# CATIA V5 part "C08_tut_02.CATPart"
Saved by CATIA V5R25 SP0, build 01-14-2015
Part number: Part1
Bounding box of the stored display mesh (mm): x -50.5 to 35, y -44.806 to 44.806, z 0 to 30
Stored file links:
  E:\ashutosh\Academics\Catia\CATIA V5-6R2013_partfiles\Tutorials_ver_2\C08_tut_02.CATPart
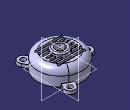
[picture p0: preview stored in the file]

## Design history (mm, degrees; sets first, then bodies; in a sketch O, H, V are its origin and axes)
Body1 (main body)
  Sketch1 on yz-plane, origin (0, 0, 0), H (0, 1, 0), V (0, 0, 1)
    line L1 (0, 0) -> (0, 25)
    line L2 (0, 25) -> (25, 25)
    point P2 (35, 25)
    line L3 (35, 15) -> (35, 0)
    point P3 (35, 0)
    line L4 (35, 0) -> (0, 0)
    reference intersected line E1 through (0, 0) direction (0, 1) from zx-plane
    axis line L5 (0, 41.2428) -> (0, -12.5007)
    point P4 (0, 41.2428)
    arc A1 centre (25, 15) radius 10 from (25, 25) to (35, 15) cw
    radius about axis P3 L5 = 35
    distance P2 P3 = 25
    radius A1 = 10
    horizontal: L2 H, L4 H
    coincidence: P3 H, L1 E1, P4 L1, L2 P2, L3 P2
    vertical: L3 V, L5 V
    tangency: A1 L2, A1 L3
  Shaft1: profile Sketch1, axis Sketch1.L5, angle 360
  Shell1: ExtOffset 0, Face face of Shaft1 from Sketch1.L4, IntOffset 3
  Sketch2 on face of Shaft1 from Sketch1.L4, origin (0, 0, 0), H (1, 0, 0), V (0, -1, 0)
    projected circle E1 centre (0, 0) radius 35 from edge [face of Shaft1 from Sketch1.L3 | face of Shaft1 from Sketch1.L4]
    projected arc E2 centre (0, 0) radius 35 from (-34.0735, 8) to (-34.0735, -8) ccw from edge [face of Shaft1 from Sketch1.L3 | face of Shaft1 from Sketch1.L4]
    point P1 (-34.0735, 8)
    line L1 (-34.0735, 8) -> (-42.5, 8)
    arc A1 centre (-42.5, 0) radius 8 from (-42.5, 8) to (-42.5, -8) ccw
    point P3 (-42.5, 0)
    line L2 (-42.5, -8) -> (-34.0735, -8)
    point P5 (-34.0735, -8)
    circle A2 centre (-42.5, 0) radius 4
    radius A1 = 8
    radius A2 = 4
    distance P3 V = 42.5
    coincidence: P1 E1, P3 H, P5 E1
    horizontal: L1 H, L2 H
    tangency: A1 L1, L2 A1
  Pad1: profile Sketch2, direction (0, 0, 1), length 5
  CircPattern1: of Pad1, instances 3, angular step 120 {= 360.0*1 deg/CircPattern1.AngularNumber}, axis from face of Shaft1 from Sketch1.L3
  Sketch3 on face of Shaft1 from Sketch1.L2, origin (0, 0, 25), H (1, 0, 0), V (0, 1, 0)
    point P1 (0, -18)
    line L1 (20, -19.75) -> (-20, -19.75)
    line L2 (-20, -16.25) -> (20, -16.25)
    point P5 (-20, -16.25)
    point P6 (20, -18)
    point P7 (-20, -18)
    arc A1 centre (20, -18) radius 1.75 from (20, -19.75) to (20, -16.25) ccw
    arc A2 centre (-20, -18) radius 1.75 from (-20, -16.25) to (-20, -19.75) ccw
    point P8 (-20, -16.25)
    axis line L3 (20, -18) -> (-20, -18)
    distance P7 P6 = 40
    distance H P6 = 18
    distance L2 L1 = 3.5
    coincidence: P1 V, A2 P5, P5 P8
    horizontal: L1 H, L2 H, L3 H
    equidistance: L1 L2 P1
    tangency: A1 L1, A2 L1, L2 A2, L2 A1
    symmetry: P7 P6 V
  Pocket1: profile Sketch3, direction (0, 0, -1), length 8
  RectPattern1: of Pocket1, direction 1 instances 7, spacing 6, along yz-plane
  Sketch4 on face of Shell1, origin (0, 0, 22), H (1, 0, 0), V (0, -1, 0)
    circle A1 centre (0, 0) radius 7.5
    circle A2 centre (0, 0) radius 12.5
    radius A2 = 12.5
    radius A1 = 7.5
  Pad2: profile Sketch4, direction (0, 0, 1), length 8
  Sketch5 on face of Pad2, origin (0, 0, 22), H (1, 0, 0), V (0, -1, 0)
    circle A1 centre (0, 0) radius 7.5
    reference projected arc E1 centre (0, 0) radius 7.5 from (7.293, -1.75) to (7.293, 1.75) ccw from edge [face of Pad2 | face of Pad2 from Sketch4.A1]
    coincidence: E1 A1
  Pocket2: profile Sketch5, direction (0, 0, 1), length 8
  Fillet1: radius 2, on edge [end face of Pad2 | face of Pad2 from Sketch4.A2]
